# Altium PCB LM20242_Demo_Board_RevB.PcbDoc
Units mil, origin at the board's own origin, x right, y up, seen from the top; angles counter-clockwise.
Board outline 2150 x 1000 mil, 2 copper layers (Top Layer, Bottom Layer); 34 components, 15 nets, 80 pads, 42 vias.
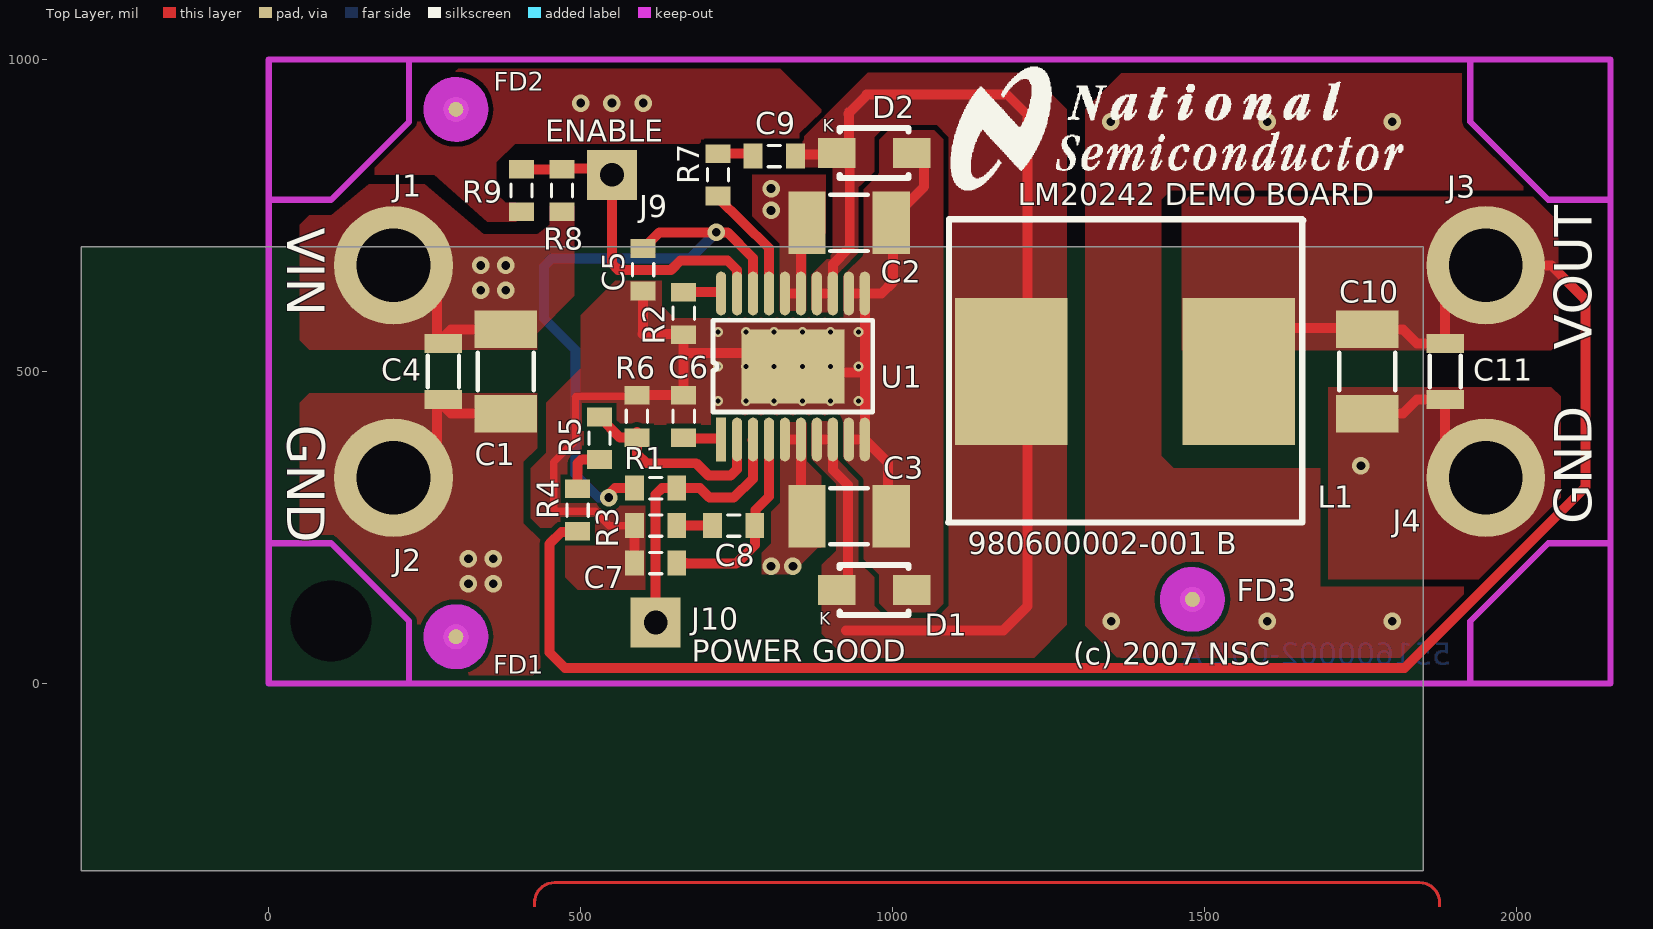
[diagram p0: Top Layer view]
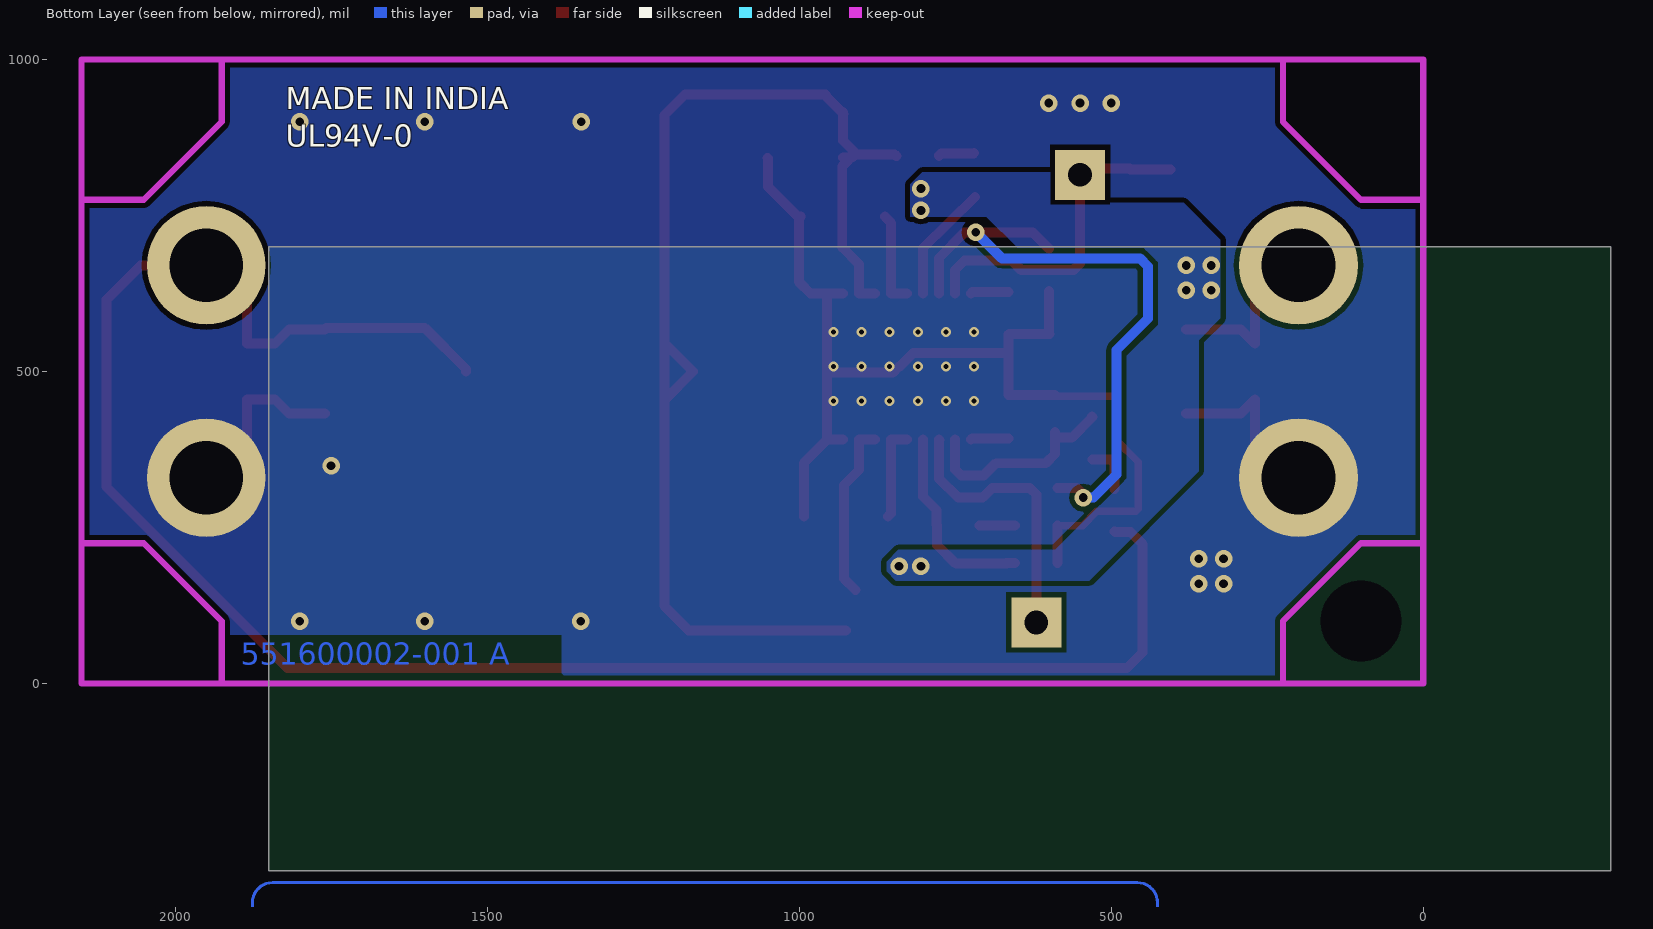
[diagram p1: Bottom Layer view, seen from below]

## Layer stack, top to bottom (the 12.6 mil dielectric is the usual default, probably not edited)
Top Layer: signal copper 1.4
Dielectric: dielectric 12.6, FR-4, Dk 4.8
Bottom Layer: signal copper 1.4

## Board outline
-300,-300 1850,-300 1850,700 -300,700

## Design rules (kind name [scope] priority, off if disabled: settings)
Clearance [All] p1: gap=8
ComponentClearance [All] p1: gap=6 collisioncheckmode=3 verticalgap=8
HoleSize [All] p1: absolutevalues=TRUE maxlimit=150 minlimit=1 maxpercent=80.000 minpercent=20.000
PolygonConnect [All] p1: connectstyle=Direct reliefconductorwidth=10 reliefentries=4 polygonreliefangle="90 Angle"
RoutingVias [All] p1: holewidth=8 width=16 viastyle="Through Hole" minholewidth=8 minwidth=8 maxholewidth=50 maxwidth=120
SolderMaskExpansion [All] p1: expansion=2
TestPointUsage [All] p1: valid=0 allowmultiple=FALSE
Testpoint [All] p1: side=15 testpointundercomponent=TRUE minsize=40 maxsize=100 preferedsize=60 minholesize=0 maxholesize=40 preferedholesize=32 testpointgrid=1 style=1023 order=0-112345678
Width [All] p1: maxlimit=50 minlimit=8 preferedwidth=8 toplayer_prefwidth=16 bottomlayer_prefwidth=16 minimp=50.000000 maximp=50.000000 favimp=50.000000
17 further rules are at their usual default settings.

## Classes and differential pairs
component class LM20242: C1 C2 C3 C4 C5 C6 C7 C8 C9 C10 C11 D1 D2 J1 J2 J3 J4 J9 J10 L1 R1 R2 R3 R4 R5 R6 R7 R8 R9 U1

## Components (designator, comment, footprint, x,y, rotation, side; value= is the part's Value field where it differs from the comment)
C1 "4.7uF" "1210 - MOD" 380,500 r270 top
C2 "4.7uF" "1210 - MOD" 930,738 r0 top
C3 "4.7uF" "1210 - MOD" 930,268 r0 top
C4 "0.1uF" "0805 - MOD" 280,500 r270 top
C5 "1uF" "0603 - MOD" 600,663 r270 top
C6 "0.1uF" "0603 - MOD" 665,428 r90 top
C7 "120pF" "0603 - MOD" 620,193 r180 top
C8 "2200pF" "0603 - MOD" 745,253 r180 top
C9 "0.1uF" "0603 - MOD" 810,845 r0 top
C10 "100uF" "1210 - MOD" 1760,500 r270 top
C11 "1uF" "0805 - MOD" 1885,500 r270 top
D1 "MBR0540" SOD-123 970,150 r180 top
D2 "MBR0540" SOD-123 970,850 r180 top
FD1 "Comment" "PCB Fiducial_0.040"#1 300,75 r90 top
FD2 "Comment" "PCB Fiducial_0.040"#2 300,920 r0 top
FD3 "Comment" "PCB Fiducial_0.040"#3 1480,135 r0 top
J1 "12VDC" PAD112#1 230,740 r0 top
J2 "GND" PAD112#2 250,310 r0 top
J3 "+3.3V @ 2A" PAD112#3 1925,730 r0 top
J4 "GND" PAD112#4 1925,245 r0 top
J9 "ENABLE" "PAD_SMALL SQU POST"#1 585,815 r0 top
J10 "POWER GOOD" "PAD_SMALL SQU POST"#2 625,98 r0 top
L1 "15uF" mss1278 1190,500 r180 top
R1 "10k" "0603 - MOD" 620,313 r0 top
R2 "205k" "0603 - MOD" 665,593 r90 top
R3 "12.1k" "0603 - MOD" 620,253 r0 top
R4 "348" "0603 - MOD" 495,278 r90 top
R5 "30.9k" "0603 - Mod" 530,393 r90 top
R6 "10k" "0603 - MOD" 590,428 r90 top
R7 "0" "0603 - MOD" 720,815 r270 top
R8 "49.9k" "0603 - MOD" 470,790 r270 top
R9 "10k" "0603 - MOD" 405,790 r90 top
U1 "LM20242" TSSOP-20-EP 840,508 r90 top
? "Comment" LOGO_WORLDMARK 1435,880 r0 top

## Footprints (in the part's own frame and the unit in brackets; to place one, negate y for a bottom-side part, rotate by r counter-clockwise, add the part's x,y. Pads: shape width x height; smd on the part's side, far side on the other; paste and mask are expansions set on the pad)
"0603 - MOD" [mil]
  rect 30x40 smd: 1(-34,0) 2(34,0)
  silkscreen extent -10,-17 10,17
"0603 - Mod" [mil]
  rect 30x40 smd: 1(-34,0) 2(34,0)
  silkscreen extent -10,-17 10,17
"0805 - MOD" [mil]
  rect 30x60 smd: 1(-45,0) 2(45,0)
  silkscreen extent -25,-25 25,25
"1210 - MOD" [mil]
  rect 60x100 smd: 1(-67.5,0) 2(67.5,0)
  silkscreen extent -30,-45 30,45
LOGO_WORLDMARK [mil] "Official NSC Logo"
  silkscreen extent -343,-89 382,108
mss1278 [mil]
  rect 180x236.22 smd: 1(0,0) 2(-364,0)
  silkscreen extent -468,-244 101,242
PAD112#1 [mil]
  round 190 hole 118: 1(-30,-70)
PAD112#2 [mil]
  round 190 hole 118: 1(-50,20)
PAD112#3 [mil]
  round 190 hole 118: 1(25,-60)
PAD112#4 [mil]
  round 190 hole 118: 1(25,85)
"PAD_SMALL SQU POST"#1 [mil]
  rect 80x80 hole 38: 1(-35,0)
"PAD_SMALL SQU POST"#2 [mil]
  rect 80x80 hole 38: 1(-5,0)
"PCB Fiducial_0.040"#1 [mil] "Orientation and alignment fiducial"
  round 40 smd mask+40: FD1(0,0)
  Top Layer keep-out circle w40: c0,0 r32
"PCB Fiducial_0.040"#2 [mil] "Orientation and alignment fiducial"
  round 40 smd mask+40: FD2(0,0)
  Top Layer keep-out circle w40: c0,0 r32
"PCB Fiducial_0.040"#3 [mil] "Orientation and alignment fiducial"
  round 40 smd mask+40: FD3(0,0)
  Top Layer keep-out circle w40: c0,0 r32
SOD-123 [mil]
  rect 60x48 smd: 1(-60,0) 2(60,0)
  silkscreen extent -55,-40 55,40
TSSOP-20-EP [mm]
  rect 1.78x0.42 smd: 1(-2.97,2.925)
  oval 1.78x0.42 smd: 2(-2.97,2.275) 3(-2.97,1.625) 4(-2.97,0.975) 5(-2.97,0.325) 6(-2.97,-0.325) 7(-2.97,-0.975) 8(-2.97,-1.625) 9(-2.97,-2.275) 10(-2.97,-2.925) 11(2.97,-2.925) 12(2.97,-2.275) 13(2.97,-1.625) 14(2.97,-0.975) 15(2.97,-0.325) 16(2.97,0.325) 17(2.97,0.975) 18(2.97,1.625) 19(2.97,2.275) 20(2.97,2.925)
  rect 3x4.2 smd: 21(0,0)
  silkscreen extent -1.85,-3.25 1.88,3.26

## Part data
C1 C2 C3 C10: library part CAP-1210, "Capacitor Ceramic X7R"
C4 C11: library part CAP-0805, "Capacitor Ceramic X7R"
C5 C6 C7 C8 C9: library part CAP-0603, "Capacitor Ceramic X7R"
D1: library part DIODE-S-SMA, "Schottky Diode"
D2: library part DIODE-S--SOD-123, "Schottky Diode"
J1: library part "Terminal, Keystone", "TEST POINT"
J2 J3 J4: library part PAD_KEYSTONE-1503-2, "TEST POINT"
J9 J10: library part "PAD_KEYSTONE-5000 Series", "TEST POINT"
L1: library part IND-MSS1278
R1 R2 R3 R4 R5 R6 R7 R8 R9: library part RES0603, "1% Thick Film"

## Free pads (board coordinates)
  round 60 hole 130 unplated: MH1(100,900) MH2(100,100) MH3(2050,900) MH4(2050,100)

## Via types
v1: diameter 28, hole 14, Top Layer to Bottom Layer, 24 vias
v2: diameter 16, hole 8, Top Layer to Bottom Layer, 18 vias

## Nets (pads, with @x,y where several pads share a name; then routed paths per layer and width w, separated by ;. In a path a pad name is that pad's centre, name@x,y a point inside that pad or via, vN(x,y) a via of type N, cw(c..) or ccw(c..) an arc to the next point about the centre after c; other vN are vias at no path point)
GND: C1.2 C2.2 C3.2 C4.2 C5.2 C6.2 C7.2 C10.2 C11.2 D1.1 D2.1 J2.1 J4.1 R2.1 R3.1 R6.2 R9.1 U1.9 U1.10 U1.11 U1.12 U1.21 | length 2405
  Top Layer w12: R3.1 546,253 523,276 461,276 457,280 457,355 491,389 491,458 493,460 588,460 R6.2
  Top Layer w16: J2.1@200,300 200,310 270,380 270,455 292.5,432.5 C1.2 ; C7.2 R3.1 ; R6.2 C6.2 R2.1 664,560 599,560 600,561 C5.2 ; 665,530 817,530 U1.21@838,509 ; U1.21 850,498 945,498 955.16,508.16 ; U1.9 U1.10 ; U1.12 981.93,624.93 1000,643 1000,745.5 997.5,748 1002,748 1050,796 1050,841 D2.1@1051,842 ; U1.11 U1.10 ; C3.2@992.5,268 992.5,353.73 U1.10 ; C10.2 1817.5,432.5 1840,455 C11.2 1885,365 J4.1@1935,315
  other v1: 1350,100 1600,100 1800,100 320,160 360,160 320,200 360,200 1750,349 1349,900 1600,900 1800,900 500,930 550,930 600,930
  other v2: 720,453 765,453 810,453 855,453 900,453 945,453 720,508 765,508 810,508 855,508 900,508 945,508 720,563 765,563 810,563 855,563 900,563 945,563
NetC1_1: C1.1 C2.1 C3.1 C4.1 J1.1 R8.2 U1.5 U1.6 U1.15 U1.16 | length 599.5
  Top Layer w16: J1.1@205,695 270,630 270,545 292.5,567.5 C1.1 ; U1.5 U1.6 852.8,272.7 C3.1@857.5,268 ; U1.16 U1.15 852.8,738.3 C2.1@862.5,748
  other v1: 805,188 840,188 340,630 380,630 340,670 380,670 805,758 805,793
NetC5_1: C5.1 R1.1 U1.18 | length 1032.6
  Top Layer w16: v1(545,298) 545,303 555,313 R1.1 ; C5.1 626,723 735,723 776.02,681.98 U1.18
  Bottom Layer w16: v1(545,298) 528.63,298 491.63,335 491.63,534.37 441,585 441,668.37 454,681.37 675.37,681.37 v1(717,723)
NetC6_1: C6.1 U1.1 | length 60.6
  Top Layer w16: C6.1@665,393 722.91,393 U1.1
NetC7_1: C7.1 C8.1 U1.4 | length 318.3
  Top Layer w16: C7.1 669,193 668,192 749,192 779,222 C8.1 780,254 780,278 801.61,299.61 U1.4
NetC8_2: C8.2 R3.2 | length 57
  Top Layer w16: R3.2 C8.2
NetC9_1: C9.1 R7.1 | length 58.7
  Top Layer w16: R7.1@720,850 721,849 773,849 776,846 C9.1
NetC9_2: C9.2 D1.2 D2.2 L1.1 U1.7 U1.8 U1.13 U1.14 | length 2243.8
  Top Layer w16: C9.2 847,848 910,848 915,843 D2.2@930,843 ; U1.7 U1.8 903.98,342.02 928,318 928,168 D1.2 ; U1.14 U1.13 903.98,671.98 930,698 ; 925,85 1177,85 1216,124 1216,911 1183,944 958,944 ; 928.62,912.62 956.62,940.62 ; 930,916 930,870 D2.2 931,829 931,699 ; L1.1@1210,540 1170,500 L1.1@1216,454
NetC10_1: C10.1 C11.1 J3.1 L1.2 R4.1 | length 3075.2
  Top Layer w16: R4.1 494,243 469,243 450,224 450,50 475,25 1820,25 2110,315 2110,615 2055,670 J3.1 ; L1.2@1534,500 1534,504 1600,570 1757.5,570 C10.1 1817.5,567.5 1840,545 C11.1 1885,625 1950,690 J3.1@1950,700
NetJ9_1: J9.1 R8.1 R9.2 U1.19 | length 514.4
  Top Layer w16: R9.2 R8.1 471,825 J9.1@540,825 ; J9.1@540,793 550,783 550,673 560,663 645,663 660,678 735,678 750.43,662.57 U1.19
NetJ10_1: J10.1 R1.2 U1.3 | length 446.8
  Top Layer w16: J10.1 620,303 630,313 691.06,313 706.06,298 744.5,298 776,328 U1.3@776,390.05 ; U1.3@775,390.05 U1.3
NetR2_2: R2.2 U1.20 | length 60.7
  Top Layer w16: R2.2 722.77,627 U1.20
NetR4_2: R4.2 R5.1 | length 78.5
  Top Layer w16: R4.2 495,353 501,359 R5.1
NetR5_2: R5.2 R6.1 U1.2 | length 337
  Top Layer w16: R5.2@531,428 R5.2 563,394 R6.1 ; R6.1@590,403 590,368 605,353 685,353 705,333 740,333 750,343 750,390.64 U1.2
NetR7_2: R7.2 U1.17 | length 189.5
  Top Layer w16: R7.2@718.5,779.5 801.61,698 U1.17
pads on no net: FD1.FD1 FD2.FD2 FD3.FD3

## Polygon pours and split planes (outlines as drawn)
GND on Top Layer "Top Layer-GND 2" (solid, pour order 1012): 66,466 50,450 50,238.25 106,238.25 105.07,237.33 237.25,105.15 237.25,16.75 240.74,13.25 423.25,13.25 435,25 435,230.24 408.24,257 408.24,355 430,376.76 430,465 65,465
GND on Top Layer "Top Layer-GND 6" (solid, pour order 1002): 1359,42 1308,93 1308,920 1366,978 1911.75,978 1911.75,899 2009.75,801 2009.75,790 1445,790 1430,775 1430,365 1450,345 1685,345 1685,155 1915,155 1915,143.07 1813.24,41.31 1365,41.31
NetC9_2 on Top Layer "Top Layer-NetC9_2 1" (solid, pour order 1009): 870,420 910,420 910,360 945,325 945,195 970,170 970,125 990,105 1070,105 1090,125 1090,875 1070,895 990,895 970,875 970,820 950,800 945,795 945,690 910,655 910,595 869,595 869,655 904,690 904,827 856,827 856,875 960,979 1220,979 1279,920 1279,115 1220,56 910,56 886,80 886,190 909,213 909,320 870,359
GND on Top Layer "Top Layer-GND" (solid, pour order 1021): 397,740 350,740 265,815 170,815 170,830 235,895 235,950 855,950 885,920 885,910 719,910 705,896 705,880 690,865 395,865 365,835 365,785 380,770 397,770
GND on Top Layer "Top Layer-GND 6" (solid, pour order 1000): 697,874 850,874 850,881.67 885,915.21 885,920 698,920 698,874
NetC10_1 on Top Layer "Top Layer-NetC10_1" (solid, pour order 1001): 1463,530 1463,769 1474,780 2026.26,780 2066.26,740 2066.26,545 2055,533.74 1463,533.74
NetC9_2 on Top Layer "Top Layer-NetC9_2" (solid, pour order 1003): 1279,120 1279,94 1226.31,41.31 1205.31,41.31 1205.31,120
NetC9_2 on Top Layer "Top Layer-NetC9_2" (solid, pour order 1004): 906,60 926,40 1204,40 1225,61 905,61
NetC1_1 on Top Layer "Top Layer-NetC1_1 3" (solid, pour order 1005): 429,560 490,621 490,660 414,660 414,560
NetC1_1 on Top Layer "Top Layer-NetC1_1 1" (solid, pour order 1007): 819,419 862,419 862,355.88 885,332.88 885,218 880,218 837,175 790,175 790,210 805,225 805,275 820,290 820,419
NetC1_1 on Top Layer "Top Layer-NetC1_1 2" (solid, pour order 1008): 861,596 861,690 892.34,721.34 892.34,815 775,815 775,749 819,705 819,597 861,597
GND on Top Layer "Top Layer-GND 1" (solid, pour order 1010): 921,597 921,656 950,685 950,793 975,818 975,874 990,889 1068,889 1081,876 1081,128 1067,114 993,114 978,129 978,174 951,201 951,329 921,359
GND on Top Layer "Top Layer-GND" (solid, pour order 1011): 1698.62,475 2055,475 2070,460 2070,279 1958,167 1698,167 1698,475
NetC1_1 on Top Layer "Top Layer-NetC1_1" (solid, pour order 1015): 490,770 490,650 430,615 430,535 125,535 100,555 100,750 160,800 250,800 345,720 430,720 450,735 450,765 490,765
NetC1_1 on Top Layer "Top Layer-NetC1_1" (solid, pour order 1020): 100,750 65,750 50,735 50,550 65,535 125,535 125,750
GND on Top Layer "Top Layer-GND 3" (solid, pour order 1013): 932,586 720,586 720,418 964,418 964,587 932,587
GND on Top Layer "Top Layer-GND 4" (solid, pour order 1014): 735,585 650,585 630,605 630,645 555,645 500,590 500,505 445,450 445,370 420,345 420,265 435,250 475,250 475,170 495,150 610,150 610,305 505,305 505,415 733,415 733,585
GND on Top Layer "Top Layer-GND 5" (solid, pour order 1016): 238.25,950 238.25,985 820,985 885,920 238,920 238,950
NetC1_1 on Bottom Layer "Bottom Layer-NetC1_1" (solid, pour order 1000): 845,165 860,180 860,195 841,214 590,214 475,329 475,525 425,575 425,675 448,698 650,698 700,748 822,748 822,800 803,819 594,819 545,770 384,770 325,711 325,585 360,550 360,340 530,170 535,165
GND on Bottom Layer "Bottom Layer-GND" (solid, pour order 1006): 15,760 100,760 235,895 235,990 1915,990 1915,895 2045,765 2140,765 2140,235 2045,235 1915,105 1915,10 235,10 235,105 105,235 10,235 10,760

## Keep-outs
Keep-Out Layer:
  lines w10: 0,225 100,225 225,100 225,0 ; 0,775 100,775 225,900 225,1000 ; 1925,0 1925,100 2050,225 2150,225 ; 1925,1000 1925,900 2050,775 2150,775 ; 0,0 2150,0 2150,1000 0,1000 0,0

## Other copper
Top Layer:
  text "Top Layer" at 486,-575.3 h32
Bottom Layer:
  text "551600002-001 A" at 1895,30 h35
  text "Bottom Layer" at 486,-669 h32
Multi-Layer:
  lines w5: 486,-502.9 1816,-502.9 ; 486,-403.6 1816,-403.6 ; 426,-753 ccw(c458,-753) 458,-785 1844,-785 ccw(c1844,-753) 1876,-753 1876,-351 ccw(c1844,-351) 1844,-319 458,-319 ccw(c458,-351) 426,-351 426,-753
  text "Layer Stack Up Detail for: LM20242.PcbDoc" at 486,-384.4 h32
  text "Layer" at 486,-440.6 h23
  text "Name" at 486,-486.6 h23

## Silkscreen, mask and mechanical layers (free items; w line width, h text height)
Top Overlay:
  text "ENABLE" at 443,868 h35
  text "LM20242 DEMO BOARD" at 1200,766 h35
  text "VIN" at 30,730 h60 r270
  text "VOUT" at 2120,535 h60 r90
  text "GND" at 30,415 h60 r270
  text "GND" at 2120,255 h60 r90
  text "980600002-001 B" at 1120,207 h35
  text "POWER GOOD" at 678,35 h35
  text "(c) 2007 NSC" at 1289,30 h35
Bottom Overlay:
  text "MADE IN INDIA" at 1823,920 h35
  text "UL94V-0" at 1823,860 h35
Drill Drawing:
  text ".LEGEND" at 2200,-177 h35
  text "Drill Drawing." at 2202,-253 h35

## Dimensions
0,0 to 2150,0 on Mechanical 1
0,0 to 0,1000 on Mechanical 1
